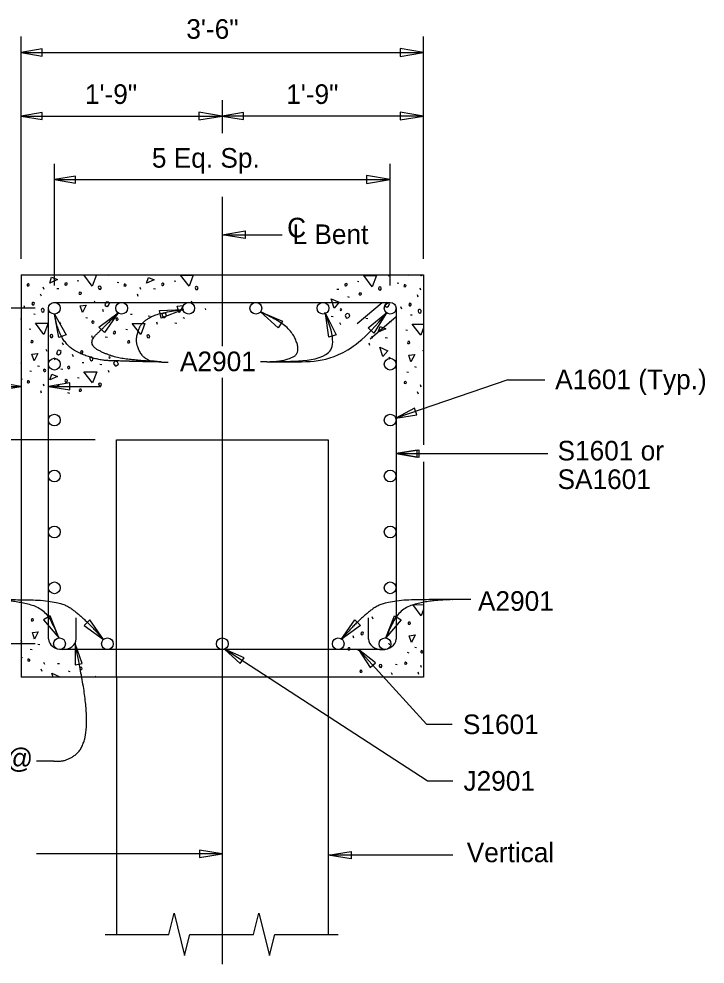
# Model space of a CAD drawing. Extents: x 437 to 537, y 571 to 720.
# Drawn here: x 507.46 to 519.49, y 668.31 to 684.9 of the extents above; entities that cross this region are included whole.
import ezdxf

# ---------------------------------------------------------------- set-up
doc = ezdxf.new("R2010")
doc.units = 0
for name, color, linetype in [('BR_AUTO DIMENSION', 7, 'Continuous'), ('BR_CENTER LINES', 7, 'Continuous'), ('BR_CONCRETE', 7, 'Continuous'), ('BR_PRESTRESSED BEAM', 7, 'Continuous'), ('BR_TABLE LINES', 7, 'Continuous'), ('BR_TEXT', 7, 'Continuous'), ('Default', 7, 'Continuous')]:
    doc.layers.add(name, color=color, linetype=linetype)

msp = doc.modelspace()

# ---------------------------------------------------------------- linework, layer by layer
at = {"layer": 'BR_AUTO DIMENSION'}
for p, q in [((514.557, 684.306), (514.144, 684.375)), ((514.144, 684.375), (514.144, 684.238)), ((514.144, 684.238), (514.557, 684.306)), ((511.027, 683.192), (510.615, 683.261)), ((510.615, 683.261), (510.615, 683.123)), ((510.615, 683.123), (511.027, 683.192)), ((514.557, 683.192), (514.144, 683.261)), ((514.144, 683.261), (514.144, 683.123)), ((514.144, 683.123), (514.557, 683.192)), ((513.971, 682.078), (513.558, 682.147)), ((513.558, 682.147), (513.558, 682.009)), ((513.558, 682.009), (513.971, 682.078)), ((511.027, 681.11), (511.426, 681.177)), ((511.426, 681.177), (511.426, 681.044)), ((511.426, 681.044), (511.027, 681.11)), ((508.084, 679.717), (508.291, 679.353)), ((508.161, 679.305), (508.084, 679.717)), ((508.864, 679.487), (509.199, 679.738)), ((509.199, 679.738), (508.963, 679.392)), ((509.927, 679.783), (510.345, 679.797)), ((509.954, 679.648), (509.927, 679.783)), ((510.345, 679.797), (509.954, 679.648)), ((511.699, 679.759), (512.083, 679.593)), ((512.009, 679.477), (511.699, 679.759)), ((512.834, 679.726), (513.024, 679.352)), ((512.893, 679.311), (512.834, 679.726)), ((513.582, 679.474), (513.905, 679.74)), ((513.905, 679.74), (513.686, 679.384)), ((512.083, 679.593), (512.009, 679.477)), ((508.291, 679.353), (508.161, 679.305)), ((508.963, 679.392), (508.864, 679.487)), ((513.024, 679.352), (512.893, 679.311)), ((513.686, 679.384), (513.582, 679.474)), ((509.965, 678.876), (510.076, 678.876)), ((511.808, 678.88), (511.697, 678.88)), ((507.499, 678.449), (507.086, 678.518)), ((516.032, 678.564), (514.068, 677.891)), ((516.032, 678.564), (516.684, 678.564)), ((507.086, 678.38), (507.499, 678.449)), ((514.074, 677.269), (514.472, 677.336)), ((514.473, 677.202), (514.074, 677.269)), ((514.472, 677.336), (514.473, 677.202)), ((515.387, 674.71), (515.061, 674.71)), ((508.008, 674.425), (507.89, 674.353)), ((508.163, 674.036), (508.008, 674.425)), ((513.892, 674.036), (514.047, 674.425)), ((514.047, 674.425), (514.165, 674.353)), ((507.89, 674.353), (508.163, 674.036)), ((508.705, 674.353), (508.606, 674.256)), ((508.606, 674.256), (508.945, 674.01)), ((508.945, 674.01), (508.705, 674.353)), ((513.11, 674.01), (513.35, 674.353)), ((513.448, 674.256), (513.11, 674.01)), ((513.35, 674.353), (513.448, 674.256)), ((514.165, 674.353), (513.892, 674.036)), ((514.617, 671.53), (511.065, 673.838)), ((514.607, 672.523), (513.417, 673.831)), ((514.607, 672.523), (515.058, 672.523)), ((507.772, 671.878), (508.012, 671.878)), ((514.617, 671.53), (515.068, 671.53)), ((511.027, 670.249), (510.629, 670.316)), ((510.629, 670.316), (510.629, 670.183)), ((510.629, 670.183), (511.027, 670.249)), ((512.885, 670.226), (513.284, 670.292)), ((513.284, 670.159), (512.885, 670.226)), ((513.284, 670.292), (513.284, 670.159))]:
    msp.add_line(p, q, dxfattribs=at)
for points in [[(507.868, 684.245), (507.868, 684.368), (507.499, 684.306)], [(507.868, 683.13), (507.868, 683.254), (507.499, 683.192)], [(511.397, 683.13), (511.397, 683.254), (511.027, 683.192)], [(508.454, 682.016), (508.454, 682.139), (508.084, 682.078)], [(508.352, 678.387), (508.352, 678.511), (507.982, 678.449)], [(514.438, 677.953), (514.398, 678.069), (514.068, 677.891)], [(514.443, 677.207), (514.443, 677.331), (514.074, 677.269)], [(508.448, 673.565), (508.57, 673.586), (508.449, 673.94)], [(511.342, 673.585), (511.409, 673.688), (511.065, 673.838)], [(513.62, 673.516), (513.712, 673.599), (513.417, 673.831)]]:
    msp.add_lwpolyline(points, close=True, dxfattribs=at)
at = {"layer": 'BR_CENTER LINES'}
msp.add_line((511.027, 676.134), (511.027, 671.862), dxfattribs=at)
at = {"layer": 'BR_CONCRETE'}
for p, q in [((507.499, 680.406), (514.557, 680.406)), ((507.499, 680.406), (507.499, 673.348)), ((514.557, 680.406), (514.557, 677.425)), ((514.557, 677.126), (514.557, 673.348)), ((508.657, 673.348), (507.499, 673.348)), ((511.462, 673.348), (508.657, 673.348)), ((513.214, 673.348), (511.462, 673.348)), ((513.835, 673.348), (513.214, 673.348)), ((514.557, 673.348), (513.835, 673.348))]:
    msp.add_line(p, q, dxfattribs=at)
at = {"layer": 'BR_PRESTRESSED BEAM'}
for p, q in [((509.17, 673.348), (509.17, 677.513)), ((509.17, 677.513), (512.885, 677.513)), ((512.885, 677.513), (512.885, 673.348)), ((509.17, 673.348), (509.17, 668.836)), ((512.885, 673.348), (512.885, 668.836))]:
    msp.add_line(p, q, dxfattribs=at)
at = {"layer": 'BR_TABLE LINES'}
for points in [[(508.974, 668.836), (510.089, 668.836), (510.182, 669.208), (510.367, 668.465), (510.46, 668.836), (511.017, 668.836)], [(511.017, 668.836), (511.575, 668.836), (511.667, 669.208), (511.853, 668.465), (511.946, 668.836), (513.061, 668.836)]]:
    msp.add_lwpolyline(points, dxfattribs=at)
at = {"layer": 'Default'}
for p, q in [((507.499, 680.684), (507.499, 684.585)), ((514.557, 680.684), (514.557, 684.585)), ((507.499, 684.306), (514.557, 684.306)), ((511.027, 683.471), (511.027, 682.892)), ((507.499, 683.192), (511.027, 683.192)), ((514.556, 683.192), (511.027, 683.192)), ((508.084, 680.22), (508.084, 682.356)), ((513.971, 680.22), (513.971, 682.356)), ((508.084, 682.078), (513.971, 682.078)), ((511.027, 681.772), (511.027, 679.156)), ((511.027, 681.11), (512.076, 681.11)), ((509.041, 680.388), (509.035, 680.406)), ((513.95, 680.376), (513.939, 680.406)), ((514.256, 680.406), (514.287, 680.398)), ((507.499, 680.279), (507.515, 680.275)), ((507.903, 680.151), (507.889, 680.189)), ((508.125, 680.169), (508.161, 680.165)), ((508.486, 680.305), (508.515, 680.299)), ((509.183, 680.278), (509.213, 680.272)), ((509.601, 680.147), (509.587, 680.185)), ((509.823, 680.165), (509.859, 680.161)), ((510.184, 680.301), (510.214, 680.295)), ((513.395, 680.293), (513.424, 680.287)), ((514.092, 680.266), (514.122, 680.26)), ((514.51, 680.136), (514.496, 680.173)), ((507.855, 680.029), (507.84, 680.069)), ((509.554, 680.025), (509.538, 680.065)), ((513.034, 680.157), (513.07, 680.153)), ((513.221, 680.025), (513.253, 680.017)), ((514.463, 680.013), (514.447, 680.053)), ((507.568, 679.82), (507.552, 679.86)), ((508.07, 679.923), (513.971, 679.923)), ((508.805, 679.907), (508.789, 679.947)), ((510.503, 679.903), (510.487, 679.943)), ((513.392, 679.55), (513.828, 679.923)), ((514.175, 679.805), (514.159, 679.844)), ((507.745, 679.82), (502.762, 679.82)), ((507.721, 679.722), (507.749, 679.718)), ((507.982, 674.018), (507.981, 679.82)), ((508.945, 679.759), (508.931, 679.797)), ((509.42, 679.718), (509.447, 679.714)), ((509.727, 679.686), (509.761, 679.681)), ((510.74, 679.795), (510.731, 679.817)), ((510.982, 679.817), (510.984, 679.817)), ((512.938, 679.679), (512.971, 679.673)), ((513.621, 679.286), (514.074, 679.673)), ((514.074, 679.82), (514.074, 677.745)), ((514.329, 679.706), (514.356, 679.702)), ((508.194, 679.541), (508.18, 679.578)), ((508.636, 679.659), (508.667, 679.651)), ((509.892, 679.537), (509.879, 679.574)), ((510.198, 679.566), (510.229, 679.558)), ((510.334, 679.655), (510.365, 679.647)), ((513.103, 679.529), (513.089, 679.566)), ((513.545, 679.647), (513.576, 679.639)), ((513.952, 679.59), (513.986, 679.584)), ((507.639, 679.458), (507.668, 679.452)), ((508.754, 679.3), (508.74, 679.338)), ((509.337, 679.454), (509.366, 679.448)), ((514.246, 679.442), (514.275, 679.436)), ((508.244, 679.172), (508.228, 679.212)), ((508.976, 679.318), (509.012, 679.314)), ((513.615, 679.166), (513.6, 679.206)), ((513.663, 679.289), (513.649, 679.326)), ((513.885, 679.306), (513.921, 679.302)), ((507.958, 679.06), (507.942, 679.099)), ((508.419, 678.969), (508.403, 679.009)), ((514.557, 679.065), (514.549, 679.084)), ((508.098, 678.912), (508.084, 678.95)), ((508.573, 678.871), (508.6, 678.867)), ((508.88, 678.839), (508.913, 678.833)), ((507.652, 678.723), (507.684, 678.715)), ((507.788, 678.812), (507.82, 678.804)), ((508.196, 678.755), (508.23, 678.749)), ((509.045, 678.69), (509.031, 678.727)), ((514.26, 678.707), (514.291, 678.699)), ((514.395, 678.796), (514.427, 678.788)), ((507.499, 678.581), (507.518, 678.577)), ((508.49, 678.607), (508.519, 678.601)), ((511.027, 678.602), (511.027, 677.673)), ((504.79, 678.449), (507.499, 678.449)), ((507.859, 678.331), (507.844, 678.37)), ((507.907, 678.453), (507.893, 678.491)), ((507.982, 678.449), (508.899, 678.449)), ((508.129, 678.471), (508.165, 678.467)), ((508.316, 678.339), (508.348, 678.331)), ((514.466, 678.315), (514.451, 678.355)), ((514.514, 678.437), (514.5, 678.475)), ((514.074, 677.745), (514.073, 674.013)), ((508.799, 677.513), (503.901, 677.513)), ((511.027, 677.673), (511.027, 668.315)), ((514.074, 677.269), (516.732, 677.269)), ((507.499, 676.524), (507.501, 676.523)), ((507.499, 674.455), (507.505, 674.454)), ((508.465, 674.018), (508.465, 674.389)), ((513.59, 674.016), (513.59, 674.388)), ((513.671, 674.366), (513.657, 674.404)), ((513.336, 674.035), (513.32, 674.075)), ((507.745, 673.934), (503.869, 673.934)), ((507.796, 673.929), (507.828, 673.922)), ((513.962, 673.907), (513.948, 673.944)), ((514.403, 673.874), (514.435, 673.866)), ((507.499, 673.7), (507.526, 673.695)), ((507.66, 673.841), (507.692, 673.833)), ((513.881, 673.831), (508.174, 673.831)), ((513.404, 673.82), (513.432, 673.816)), ((514.268, 673.785), (514.299, 673.777)), ((507.914, 673.571), (507.901, 673.608)), ((508.137, 673.588), (508.173, 673.585)), ((514.066, 673.574), (514.096, 673.568)), ((514.522, 673.515), (514.508, 673.553)), ((507.867, 673.449), (507.852, 673.488)), ((508.324, 673.457), (508.356, 673.449)), ((508.808, 673.348), (508.801, 673.366)), ((514.011, 673.387), (513.996, 673.427)), ((514.474, 673.393), (514.459, 673.433)), ((511.027, 670.249), (507.772, 670.249)), ((515.068, 670.226), (512.885, 670.226))]:
    msp.add_line(p, q, dxfattribs=at)
for points in [[(508.001, 680.262), (508.033, 680.364), (508.137, 680.323), (508.001, 680.262)], [(508.748, 680.209), (508.598, 680.406), (508.821, 680.404), (508.748, 680.209)], [(509.608, 680.406), (509.611, 680.406), (509.612, 680.406)], [(509.699, 680.258), (509.731, 680.36), (509.835, 680.319), (509.699, 680.258)], [(510.446, 680.205), (510.296, 680.402), (510.519, 680.4), (510.446, 680.205)], [(513.657, 680.197), (513.507, 680.394), (513.73, 680.392), (513.657, 680.197)], [(514.496, 680.406), (514.506, 680.396)], [(514.506, 680.396), (514.52, 680.394), (514.533, 680.4), (514.535, 680.406)], [(507.605, 680.216), (507.627, 680.211), (507.641, 680.22), (507.643, 680.234), (507.639, 680.238), (507.623, 680.246), (507.609, 680.244), (507.607, 680.23), (507.605, 680.216)], [(508.277, 680.222), (508.285, 680.222), (508.301, 680.23), (508.307, 680.248), (508.305, 680.258), (508.289, 680.266), (508.269, 680.254), (508.265, 680.242), (508.269, 680.23), (508.277, 680.222)], [(508.858, 680.173), (508.868, 680.155), (508.892, 680.151), (508.902, 680.169), (508.905, 680.185), (508.896, 680.195), (508.878, 680.205), (508.86, 680.199), (508.854, 680.181), (508.858, 680.173)], [(509.303, 680.212), (509.325, 680.207), (509.339, 680.216), (509.341, 680.23), (509.337, 680.234), (509.321, 680.242), (509.307, 680.24), (509.305, 680.226), (509.303, 680.212)], [(509.975, 680.218), (509.983, 680.218), (509.999, 680.226), (510.005, 680.244), (510.003, 680.254), (509.987, 680.262), (509.967, 680.25), (509.963, 680.238), (509.967, 680.226), (509.975, 680.218)], [(510.556, 680.169), (510.566, 680.151), (510.59, 680.147), (510.6, 680.165), (510.604, 680.181), (510.594, 680.191), (510.576, 680.201), (510.558, 680.195), (510.552, 680.177), (510.556, 680.169)], [(513.186, 680.211), (513.194, 680.211), (513.21, 680.218), (513.215, 680.236), (513.214, 680.246), (513.198, 680.254), (513.178, 680.242), (513.174, 680.23), (513.178, 680.218), (513.186, 680.211)], [(513.767, 680.161), (513.777, 680.144), (513.801, 680.14), (513.81, 680.157), (513.814, 680.173), (513.805, 680.183), (513.787, 680.193), (513.769, 680.187), (513.763, 680.169), (513.767, 680.161)], [(514.212, 680.201), (514.234, 680.195), (514.248, 680.205), (514.25, 680.218), (514.246, 680.222), (514.23, 680.23), (514.216, 680.228), (514.214, 680.214), (514.212, 680.201)], [(508.521, 680.065), (508.545, 680.065), (508.557, 680.077), (508.551, 680.098), (508.525, 680.1), (508.521, 680.088), (508.515, 680.078), (508.521, 680.065), (508.517, 680.069)], [(513.43, 680.053), (513.454, 680.053), (513.466, 680.065), (513.46, 680.086), (513.434, 680.088), (513.43, 680.077), (513.424, 680.067), (513.43, 680.053), (513.426, 680.057)], [(507.69, 679.895), (507.7, 679.878), (507.721, 679.88), (507.731, 679.893), (507.733, 679.915), (507.719, 679.921), (507.71, 679.923), (507.698, 679.919), (507.694, 679.915), (507.69, 679.895)], [(508.575, 679.744), (508.537, 679.86), (508.642, 679.874), (508.575, 679.744)], [(508.976, 679.866), (509.002, 679.852), (509.035, 679.866), (509.049, 679.907), (509.03, 679.927), (509.004, 679.933), (508.992, 679.925), (508.978, 679.903), (508.969, 679.885), (508.976, 679.866)], [(510.273, 679.74), (510.235, 679.856), (510.34, 679.87), (510.273, 679.74)], [(512.991, 679.823), (512.938, 679.986), (513.078, 679.925), (512.991, 679.823)], [(513.885, 679.854), (513.911, 679.84), (513.944, 679.854), (513.958, 679.895), (513.938, 679.915), (513.913, 679.921), (513.901, 679.913), (513.887, 679.891), (513.877, 679.874), (513.885, 679.854)], [(514.297, 679.88), (514.307, 679.862), (514.329, 679.864), (514.338, 679.878), (514.34, 679.899), (514.327, 679.905), (514.317, 679.907), (514.305, 679.903), (514.301, 679.899), (514.297, 679.88)], [(507.852, 679.785), (507.863, 679.761), (507.883, 679.75), (507.899, 679.761), (507.907, 679.773), (507.907, 679.797), (507.889, 679.815), (507.867, 679.813), (507.857, 679.803), (507.852, 679.785)], [(509.969, 679.696), (509.995, 679.655), (510.02, 679.657), (510.03, 679.667), (510.052, 679.689), (510.038, 679.722), (510.011, 679.738), (509.991, 679.73), (509.975, 679.714), (509.969, 679.696)], [(513.101, 679.783), (513.123, 679.793), (513.115, 679.801), (513.101, 679.807), (513.095, 679.793), (513.101, 679.783)], [(513.18, 679.689), (513.206, 679.647), (513.231, 679.649), (513.241, 679.659), (513.263, 679.681), (513.249, 679.714), (513.221, 679.73), (513.202, 679.722), (513.186, 679.706), (513.18, 679.689)], [(514.459, 679.769), (514.47, 679.746), (514.49, 679.734), (514.506, 679.746), (514.514, 679.757), (514.514, 679.781), (514.496, 679.799), (514.474, 679.797), (514.464, 679.787), (514.459, 679.769)], [(507.499, 679.624), (507.501, 679.627), (507.499, 679.638)], [(507.901, 679.361), (507.751, 679.558), (507.974, 679.556), (507.901, 679.361)], [(508.75, 679.56), (508.764, 679.558), (508.777, 679.564), (508.781, 679.576), (508.776, 679.586), (508.764, 679.594), (508.75, 679.6), (508.742, 679.584), (508.738, 679.572), (508.75, 679.56)], [(509.168, 679.616), (509.179, 679.604), (509.191, 679.612), (509.199, 679.623), (509.195, 679.643), (509.185, 679.645), (509.171, 679.643), (509.16, 679.631), (509.168, 679.616)], [(509.599, 679.357), (509.449, 679.555), (509.672, 679.553), (509.599, 679.357)], [(513.761, 679.399), (513.793, 679.501), (513.897, 679.46), (513.761, 679.399)], [(514.508, 679.346), (514.358, 679.543), (514.557, 679.541)], [(508.011, 679.326), (508.021, 679.308), (508.045, 679.304), (508.054, 679.322), (508.058, 679.338), (508.048, 679.348), (508.031, 679.357), (508.013, 679.352), (508.007, 679.334), (508.011, 679.326)], [(509.128, 679.371), (509.136, 679.371), (509.152, 679.379), (509.158, 679.397), (509.156, 679.407), (509.14, 679.415), (509.12, 679.403), (509.116, 679.391), (509.12, 679.379), (509.128, 679.371)], [(509.709, 679.322), (509.719, 679.304), (509.743, 679.3), (509.753, 679.318), (509.757, 679.334), (509.747, 679.344), (509.729, 679.354), (509.711, 679.348), (509.705, 679.33), (509.709, 679.322)], [(514.557, 679.477), (514.508, 679.346)], [(507.674, 679.218), (507.698, 679.218), (507.71, 679.229), (507.704, 679.251), (507.678, 679.253), (507.674, 679.241), (507.668, 679.231), (507.674, 679.218), (507.67, 679.222)], [(509.372, 679.214), (509.396, 679.214), (509.408, 679.226), (509.402, 679.247), (509.376, 679.249), (509.372, 679.237), (509.366, 679.227), (509.372, 679.214), (509.368, 679.218)], [(514.281, 679.202), (514.305, 679.202), (514.317, 679.214), (514.311, 679.235), (514.285, 679.237), (514.281, 679.226), (514.275, 679.216), (514.281, 679.202), (514.277, 679.206)], [(507.727, 678.896), (507.69, 679.013), (507.794, 679.027), (507.727, 678.896)], [(508.129, 679.019), (508.155, 679.005), (508.188, 679.019), (508.202, 679.06), (508.182, 679.08), (508.157, 679.086), (508.145, 679.078), (508.131, 679.056), (508.121, 679.038), (508.129, 679.019)], [(508.541, 679.044), (508.551, 679.027), (508.573, 679.028), (508.582, 679.042), (508.584, 679.064), (508.571, 679.07), (508.561, 679.072), (508.549, 679.068), (508.545, 679.064), (508.541, 679.044)], [(513.842, 678.971), (513.789, 679.135), (513.929, 679.074), (513.842, 678.971)], [(514.334, 678.881), (514.297, 678.997), (514.402, 679.011), (514.334, 678.881)], [(507.499, 678.837), (507.507, 678.845), (507.499, 678.865)], [(508.703, 678.934), (508.714, 678.91), (508.734, 678.898), (508.75, 678.91), (508.758, 678.922), (508.758, 678.946), (508.74, 678.963), (508.718, 678.961), (508.708, 678.952), (508.703, 678.934)], [(509.043, 678.944), (509.065, 678.954), (509.057, 678.961), (509.043, 678.967), (509.037, 678.954), (509.043, 678.944)], [(509.122, 678.849), (509.148, 678.808), (509.173, 678.81), (509.183, 678.82), (509.205, 678.841), (509.191, 678.875), (509.164, 678.891), (509.144, 678.883), (509.128, 678.867), (509.122, 678.849)], [(513.952, 678.932), (513.974, 678.942), (513.966, 678.95), (513.952, 678.956), (513.946, 678.942), (513.952, 678.932)], [(507.903, 678.713), (507.917, 678.711), (507.93, 678.717), (507.934, 678.729), (507.928, 678.739), (507.917, 678.747), (507.903, 678.753), (507.895, 678.737), (507.891, 678.725), (507.903, 678.713)], [(508.32, 678.768), (508.332, 678.757), (508.344, 678.765), (508.352, 678.776), (508.348, 678.796), (508.338, 678.798), (508.324, 678.796), (508.312, 678.784), (508.32, 678.768)], [(508.752, 678.51), (508.602, 678.707), (508.825, 678.705), (508.752, 678.51)], [(507.609, 678.518), (507.631, 678.512), (507.645, 678.522), (507.647, 678.536), (507.643, 678.54), (507.627, 678.548), (507.613, 678.546), (507.611, 678.532), (507.609, 678.518)], [(508.005, 678.564), (508.037, 678.666), (508.141, 678.625), (508.005, 678.564)], [(508.281, 678.524), (508.289, 678.524), (508.305, 678.532), (508.311, 678.55), (508.308, 678.56), (508.293, 678.568), (508.273, 678.556), (508.269, 678.544), (508.273, 678.532), (508.281, 678.524)], [(508.862, 678.475), (508.872, 678.457), (508.896, 678.453), (508.905, 678.471), (508.909, 678.487), (508.9, 678.497), (508.882, 678.506), (508.864, 678.5), (508.858, 678.483), (508.862, 678.475)], [(514.216, 678.503), (514.238, 678.497), (514.252, 678.506), (514.254, 678.52), (514.25, 678.524), (514.234, 678.532), (514.22, 678.53), (514.218, 678.516), (514.216, 678.503)], [(508.525, 678.366), (508.549, 678.366), (508.561, 678.378), (508.555, 678.4), (508.529, 678.402), (508.525, 678.39), (508.519, 678.38), (508.525, 678.366), (508.521, 678.37)], [(514.516, 674.424), (514.366, 674.62), (514.557, 674.619)], [(514.557, 674.534), (514.516, 674.424)], [(507.682, 674.335), (507.706, 674.335), (507.718, 674.347), (507.711, 674.369), (507.686, 674.371), (507.682, 674.359), (507.676, 674.349), (507.682, 674.335), (507.678, 674.339)], [(514.289, 674.28), (514.313, 674.28), (514.325, 674.291), (514.319, 674.313), (514.293, 674.315), (514.289, 674.303), (514.283, 674.293), (514.289, 674.28), (514.285, 674.284)], [(507.735, 674.014), (507.698, 674.13), (507.802, 674.144), (507.735, 674.014)], [(513.458, 674.11), (513.468, 674.093), (513.489, 674.094), (513.499, 674.108), (513.501, 674.13), (513.487, 674.136), (513.478, 674.138), (513.466, 674.134), (513.462, 674.13), (513.458, 674.11)], [(514.342, 673.959), (514.305, 674.075), (514.409, 674.089), (514.342, 673.959)], [(507.499, 673.947), (507.515, 673.963), (507.501, 673.996), (507.499, 673.998)], [(513.237, 673.834), (513.249, 673.823), (513.261, 673.831), (513.269, 673.842), (513.265, 673.862), (513.255, 673.864), (513.241, 673.862), (513.229, 673.85), (513.237, 673.834)], [(514.518, 673.775), (514.531, 673.773), (514.545, 673.779), (514.549, 673.791), (514.543, 673.801), (514.531, 673.809), (514.518, 673.815), (514.51, 673.799), (514.506, 673.787), (514.518, 673.775)], [(507.617, 673.636), (507.639, 673.63), (507.652, 673.64), (507.654, 673.654), (507.65, 673.657), (507.635, 673.665), (507.621, 673.663), (507.619, 673.65), (507.617, 673.636)], [(513.779, 673.541), (513.789, 673.523), (513.812, 673.519), (513.822, 673.537), (513.826, 673.553), (513.816, 673.563), (513.799, 673.572), (513.781, 673.567), (513.775, 673.549), (513.779, 673.541)], [(514.224, 673.58), (514.246, 673.574), (514.26, 673.584), (514.261, 673.598), (514.258, 673.602), (514.242, 673.61), (514.228, 673.608), (514.226, 673.594), (514.224, 673.58)], [(508.063, 673.348), (508.041, 673.417), (508.18, 673.356), (508.173, 673.348)], [(508.533, 673.484), (508.557, 673.484), (508.569, 673.496), (508.563, 673.518), (508.537, 673.52), (508.533, 673.508), (508.527, 673.498), (508.533, 673.484), (508.529, 673.488)], [(513.442, 673.433), (513.466, 673.433), (513.478, 673.444), (513.472, 673.466), (513.446, 673.468), (513.442, 673.456), (513.436, 673.446), (513.442, 673.433), (513.438, 673.436)]]:
    msp.add_lwpolyline(points, dxfattribs=at)
for centre in [(508.084, 679.82), (509.262, 679.82), (510.439, 679.82), (511.616, 679.82), (512.793, 679.82), (513.971, 679.82), (508.084, 678.839), (513.971, 678.839), (508.084, 677.858), (513.971, 677.858), (508.084, 676.877), (513.971, 676.877), (508.084, 675.896), (513.971, 675.896), (508.084, 674.915), (513.971, 674.915), (508.174, 673.934), (509.014, 673.934), (511.027, 673.934), (513.06, 673.934), (513.881, 673.934)]:
    msp.add_circle(centre, 0.103, dxfattribs=at)
for centre, end_param in [((508.224, 674.018), 6.283185), ((513.832, 674.016), 6.266089)]:
    msp.add_ellipse(centre, major_axis=(0.241, 0), ratio=0.769287, start_param=3.141593, end_param=end_param, dxfattribs=at)
for points, degree in [([(509.965, 678.876), (509.507, 678.884), (509.312, 678.893), (508.798, 678.905), (508.174, 679.197), (508.084, 679.717)], 2), ([(509.964, 678.876), (509.564, 678.901), (509.087, 678.962), (508.643, 679.193), (509.005, 679.536), (509.206, 679.746)], 2), ([(509.951, 678.876), (509.949, 678.877), (509.95, 678.877), (509.669, 678.905), (509.506, 679.193), (509.547, 679.425), (509.633, 679.588), (509.913, 679.744), (510.345, 679.797)], 2), ([(511.808, 678.88), (511.808, 678.88), (512.101, 678.894), (512.41, 679.024), (512.233, 679.475), (511.699, 679.759), (511.699, 679.759)], 2), ([(511.808, 678.88), (511.808, 678.88), (511.808, 678.88), (512.253, 678.887), (512.932, 678.935), (513.03, 679.258), (512.825, 679.747)], 3), ([(511.808, 678.88), (511.808, 678.88), (511.808, 678.88), (512.536, 678.873), (513.013, 678.934), (513.533, 679.264), (513.905, 679.74)], 3), ([(506.993, 674.71), (506.993, 674.71), (506.993, 674.71), (508.174, 674.702), (508.576, 674.407), (508.945, 674.01), (508.945, 674.01)], 2), ([(506.993, 674.71), (506.993, 674.71), (506.993, 674.71), (507.431, 674.686), (507.926, 674.547), (508.163, 674.036), (508.163, 674.036)], 2), ([(515.06, 674.71), (515.06, 674.71), (515.06, 674.71), (513.88, 674.702), (513.478, 674.407), (513.109, 674.01), (513.109, 674.01)], 2), ([(515.06, 674.71), (515.06, 674.71), (515.06, 674.71), (514.623, 674.686), (514.128, 674.547), (513.89, 674.036), (513.89, 674.036)], 2), ([(508.012, 671.878), (508.012, 671.878), (508.317, 671.875), (508.62, 672.126), (508.667, 672.809), (508.449, 673.94), (508.449, 673.94)], 2)]:
    msp.add_open_spline(points, degree=degree, dxfattribs=at)

# ---------------------------------------------------------------- texts
at = {"layer": 'BR_TEXT'}
for s, height, p in [('3\'-6"', 0.3438, (510.397, 684.547)), ('1\'-9"', 0.3438, (508.619, 683.404)), ('1\'-9"', 0.3438, (512.148, 683.404)), ('5 Eq. Sp.', 0.3438, (509.793, 682.286)), ('C', 0.344, (512.164, 681.063)), ('L Bent', 0.3438, (512.259, 680.946)), ('A2901', 0.3438, (510.286, 678.716)), ('A1601 (Typ.)', 0.34375, (516.863, 678.4)), ('S1601 or', 0.3438, (516.905, 677.15)), ('SA1601', 0.3438, (516.905, 676.649)), ('A2901', 0.3438, (515.51, 674.512)), ('S1601', 0.3438, (515.246, 672.349)), ('SA1601 @', 0.3438, (505.48, 671.754)), ('J2901', 0.3438, (515.256, 671.357)), ('Vertical', 0.3438, (515.313, 670.102))]:
    msp.add_text(s, height=height, dxfattribs=at).set_placement(p)

doc.saveas('drawing.dxf')
